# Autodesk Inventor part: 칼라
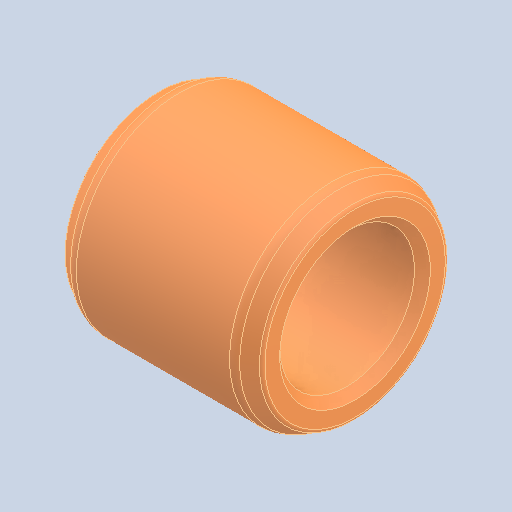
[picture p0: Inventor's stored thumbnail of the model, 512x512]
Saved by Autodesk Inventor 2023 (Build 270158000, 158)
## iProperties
Created: 2025-03
Part Number: 칼라
Material: 강철, 연강
Document SubType Name: Modeling
Designer: User
Density: 7.86 g/cm^3
Appearance: 기본값
Author: jhkim
Sending System: Autodesk Inventor 2025
Preprocessor: ST-DEVELOPER v20
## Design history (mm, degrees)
feature "솔리드1"
node "솔리드2"
